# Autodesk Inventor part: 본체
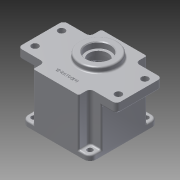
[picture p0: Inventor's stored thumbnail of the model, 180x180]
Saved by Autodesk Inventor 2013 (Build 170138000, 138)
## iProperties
Created: 2015-07
Part Number: 본체
Material: 알루미늄 6061
Document SubType Name: Modeling
Designer: user
Density: 2.71 g/cm^3
Mass: 705.306 g
Surface Area: 672.938 cm^2
Volume: 260.26 cm^3
Author: user
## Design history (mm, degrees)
sketch "스케치1"
  geometry: L1 (-37, 45)-(37, 45); L2 (45, 37)-(45, -37); L3 (37, -45)-(-37, -45); L4 (-45, -37)-(-45, 37); A1 r 8 centre (-37, 37) between (-37, 45) and (-45, 37); A2 r 8 centre (-37, -37) between (-45, -37) and (-37, -45); A3 r 8 centre (37, -37) between (37, -45) and (45, -37); A4 r 8 centre (37, 37) between (45, 37) and (37, 45); 6 further points
  constraints: 8 end point, 8 point on circle, 8 tangent, 6 point on line, 4 centre point, 3 equal radius, 2 midpoint, 2 parallel, 1 horizontal, 1 horizontal alignment, 1 perpendicular, 1 vertical alignment
  dimensions: "d0" = 90 distance of point (45, -45) point (-45, -45); "d1" = 90 distance of point (45, 45) point (45, -45); "d2" = 8 radius of A1
extrude "돌출1" new body sketch "스케치1" distance "d3" = 70; taper "d4" = 0 deg
sketch "스케치2"
  geometry: L1 (37, 45)-(-37, 45) reference; L2 (0, 45)-(0, 30); L3 (0, 30)-(60, 30); L4 (65, 25)-(65, -25); L5 (60, -30)-(-60, -30); L6 (-65, -25)-(-65, 25); L7 (-60, 30)-(0, 30); A1 r 5 centre (-60, 25) between (-60, 30) and (-65, 25); A2 r 5 centre (-60, -25) between (-65, -25) and (-60, -30); A3 r 5 centre (60, -25) between (60, -30) and (65, -25); A4 r 5 centre (60, 25) between (65, 25) and (60, 30); 5 further points
  constraints: 12 end point, 8 point on circle, 8 point on line, 8 tangent, 4 centre point, 4 perpendicular, 3 equal radius, 1 midpoint, 1 parallel
  dimensions: "d5" = 15 distance of L2.start L2.end; "d6" = 65 distance of L2.end point (65, 30); "d7" = 60 distance of point (65, 30) point (65, -30); "d8" = 130 distance of point (65, -30) point (-65, -30); "d9" = 60 distance of point (-65, -30) point (-65, 30); "d10" = 5 radius of A1
extrude "돌출2" join sketch "스케치2" distance "d11" = 12; taper "d12" = 0 deg
sketch "스케치3"
  geometry: L1 (-60, -30)-(-45, -30) reference; L2 (0, 0)-(0, 11); C1 r 25 at (0, 11)
  constraints: 2 end point, 1 centre point, 1 coincident, 1 perpendicular
  dimensions: "d13" = 11 distance of L2.start L2.end; "d14" = 25 radius of C1
extrude "돌출3" join sketch "스케치3" distance "d15" = 7; taper "d16" = 0 deg
sketch "스케치4"
  geometry: C1 r 25 at (0, 0) reference; C2 r 16 at (0, 0); 1 further point
  constraints: 1 centre point, 1 coincident
  dimensions: "d17" = 16 radius of C2
extrude "돌출4" cut sketch "스케치4" distance "d18" = 8; taper "d19" = 0 deg
sketch "스케치5"
  geometry: C1 r 16 at (0, 0) reference; C2 r 12.5 at (0, 0); 1 further point
  constraints: 1 centre point, 1 coincident
  dimensions: "d20" = 12.5 radius of C2
extrude "돌출5" cut sketch "스케치5" distance "d21" = 5; taper "d22" = 0 deg
sketch "스케치6"
  geometry: C1 r 12.5 at (0, 0) reference; C2 r 17.5 at (0, 0); 1 further point
  constraints: 1 centre point, 1 coincident
  dimensions: "d23" = 17.5 radius of C2
extrude "돌출6" cut sketch "스케치6" distance "d24" = 10; taper "d25" = 0 deg
sketch "스케치7"
  geometry: C1 r 40 at (0, 0); 1 further point
  constraints: 1 centre point, 1 coincident
  dimensions: "d26" = 40 radius of C1
extrude "돌출7" cut sketch "스케치7" distance "d27" = 9; taper "d28" = 0 deg
sketch "스케치8"
  geometry: C1 r 40 at (0, 0) reference; C2 r 39 at (0, 0)
  constraints: 1 centre point, 1 coincident
  dimensions: "d29" = 39 radius of C2
extrude "돌출8" cut sketch "스케치8" distance "d30" = 45; taper "d31" = 0 deg
sketch "스케치11"
  geometry: L1 (0, 0)-(0, 11); L2 (0, 0)-(0, -20); C1 r 17.5 at (0, 11) reference; C2 r 39 at (0, 0) reference; C3 r 39 at (0, 0); A1 r 3 centre (12.742, -8.746) between (11.115, -6.225) and (10.493, -10.732); A2 r 3 centre (-12.742, -8.746) between (-10.493, -10.732) and (-11.115, -6.225); A3 r 20.5 centre (0, 11) between (11.115, -6.225) and (-11.115, -6.225); A4 r 14 centre (0, -20) between (-10.493, -10.732) and (10.493, -10.732)
  constraints: 8 point on circle, 5 centre point, 4 end point, 4 tangent, 3 coincident, 1 collinear, 1 concentric, 1 vertical
  dimensions: "d51" = 20 distance of L1.start L2.end; "d53" = 3 radius of A1; "d54" = 3 radius of A2; "d55" = 20.5 radius of A3; "d56" = 14 radius of A4
extrude "돌출11" cut sketch "스케치11" distance "d57" = 7; taper "d58" = 0 deg
sketch "스케치12"
  geometry: L1 (0, 0)-(21.92, 21.92); L2 (0, 0)-(0, 35); C1 r 39 at (0, 0) reference; A1 r 35 centre (0, 0) between (21.763, 27.411) and (27.411, 21.763); A2 r 4 centre (24.749, 24.749) between (21.809, 27.462) and (27.462, 21.809); A3 r 3.5 centre (19.238, 29.836) between (21.762, 27.412) and (21.134, 32.777); A4 r 3.5 centre (29.836, 19.238) between (32.777, 21.134) and (27.412, 21.762); A5 r 39 centre (0, 0) between (32.777, 21.134) and (21.134, 32.777)
  constraints: 18 point on circle, 5 centre point, 5 tangent, 4 end point, 2 coincident, 1 concentric, 1 vertical
  dimensions: "d59" = 35 radius of A1; "d60" = 45 deg angle of L2 L1; "d62" = 4 radius of A2; "d63" = 3.5 radius of A3; "d65" = 3.5 radius of A4; "d66" = 8.23284 distance from line of A4.start L1
extrude "돌출12" join sketch "스케치12" distance "d67" = 52; taper "d68" = 0 deg
sketch "스케치13"
  geometry: C1 r 11 at (0, -20); A1 r 14 centre (0, -20) between (-10.493, -10.732) and (10.493, -10.732) reference; 1 further point
  constraints: 1 centre point, 1 coincident
  dimensions: "d72" = 11 radius of C1
extrude "돌출13" cut sketch "스케치13" distance "d73" = 7; taper "d74" = 0 deg
sketch "스케치14"
  geometry: C1 r 11 at (0, 0) reference; C2 r 9.5 at (0, 0); 1 further point
  constraints: 1 centre point, 1 coincident
  dimensions: "d75" = 9.5 radius of C2
extrude "돌출14" cut sketch "스케치14" distance "d76" = 1; taper "d77" = 0 deg
fillet "모깎기1" dims "d78" = 0.3
fillet "모깎기2" dims "d79" = 2
chamfer "모따기1" distance "d80" = 1; stored, may be unused: second distance "d81" = 2, angle "d82" = 45 deg
fillet "모깎기3" dims "d83" = 2
sketch "스케치15"
  geometry: L1 (37, 45)-(-37, 45) reference; L2 (-45, 37)-(-45, 30) reference; L3 (-60, -30)-(-45, -30) reference; L4 (-30, 45)-(-30, 35); L5 (-35, 30)-(-45, 30); A1 r 8 centre (-37, 37) between (-37, 45) and (-45, 37) reference; A2 r 5 centre (-35, 35) between (-35, 30) and (-30, 35); 2 further points
  constraints: 4 end point, 3 point on line, 2 perpendicular, 2 point on circle, 2 tangent, 1 centre point
  dimensions: "d84" = 15 distance of point (-30, 30) L2.end; "d85" = 5 radius of A2
extrude "돌출15" cut sketch "스케치15" distance "d86" = 63; taper "d87" = 0 deg
sketch "스케치16"
  geometry: L1 (-37, 45)-(-30, 45) reference; L2 (-37, 37)-(-37, 45); L3 (-37, 37)-(-45, 37); C1 r 3.5 at (-37, 37); A1 r 8 centre (-37, 37) between (-37, 45) and (-45, 37) reference; 1 further point
  constraints: 4 end point, 2 perpendicular, 1 centre point, 1 coincident
  dimensions: "d91" = 3.5 radius of C1
extrude "돌출16" cut sketch "스케치16" stored distance "d93" = 63; taper "d94" = 0 deg
sketch "스케치17"
  geometry: L1 (-35, 30)-(-60, 30) reference; L2 (-65, 25)-(-65, -25) reference; L3 (60, 30)-(35, 30) reference; L4 (-55, 30)-(-55, 17.5); L5 (-55, 17.5)-(-65, 17.5); C1 r 4.5 at (-55, 17.5); 1 further point
  constraints: 4 end point, 2 perpendicular, 2 point on line, 1 centre point, 1 coincident
  dimensions: "d98" = 12.5 distance of L4.start L4.end; "d99" = 10 distance of L4.end L5.end; "d100" = 4.5 radius of C1
extrude "돌출17" cut sketch "스케치17" stored distance "d101" = 63; taper "d102" = 0 deg
fillet "모깎기4" dims "d103" = 2
sketch "스케치18"
  geometry: L1 (-30, -45)-(30, -45) reference; L2 (60, 30)-(35, 30) reference; L3 (0, -45)-(0, -30); 2 further points
  constraints: 2 end point, 1 coincident, 1 midpoint, 1 perpendicular, 1 other
  dimensions: "d104" = 15 distance of L3.start L3.end
feature "엠보싱1" sketch "스케치18" dims "d5" = 15, "d6" = 65, "d7" = 60, "d8" = 130, "d9" = 60, "d10" = 5, "d105" = 0.5, "d106" = 0
sketch "스케치19"
  geometry: A1 r 4 centre (-24.749, 24.749) between (-27.462, 21.809) and (-21.809, 27.462) reference
hole "구멍1" sketch "스케치19" at (-24.749, 24.749) diameter "d107" = 3.459; stored, may be unused: countersink angle "d111" = 90 deg, drill point angle "d113" = 118 deg; dims "d108" = 12, "d109" = 4, "d110" = 2, "d112" = 15
fillet "모깎기5" dims "d117" = 2
fillet "모깎기6" dims "d118" = 2
fillet "모깎기7" dims "d119" = 2
fillet "모깎기8" dims "d120" = 2
fillet "모깎기9" dims "d121" = 2
node "솔리드1"
pattern_circular "원형 패턴1" dims angle "d70" = 360 deg
pattern_circular "원형 패턴2" dims angle "d89" = 360 deg
pattern_circular "원형 패턴3" dims angle "d96" = 360 deg
mirror "대칭1"
mirror "대칭2"
pattern_circular "원형 패턴4" dims angle "d115" = 360 deg
other parameters: "d34" = 14, "d50" = 20.5, "d52" = 14
